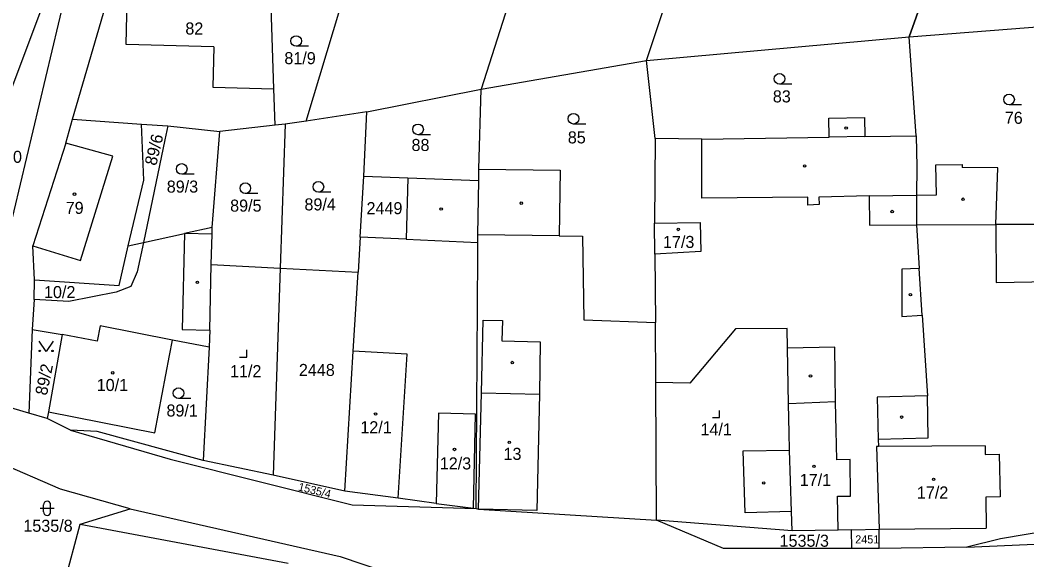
# Model space of a CAD drawing. Extents: x -801826 to -800592, y -1032871 to -1031813.
# Drawn here: x -801600 to -801458.2, y -1032298.8 to -1032222.7 of the extents above; entities that cross this region are included whole.
import ezdxf

# ---------------------------------------------------------------- set-up
doc = ezdxf.new("R2010")
doc.units = 0
for name, color, linetype in [('Vrstva 1', 7, 'Continuous'), ('Vrstva 18', 7, 'Continuous'), ('Vrstva 19', 7, 'Continuous'), ('Vrstva 25', 7, 'Continuous'), ('Vrstva 4', 7, 'Continuous')]:
    doc.layers.add(name, color=color, linetype=linetype)

msp = doc.modelspace()

# ---------------------------------------------------------------- linework, layer by layer
at = {"layer": 'Vrstva 1'}
for p, q in [((-801518.17, -1032179.53), (-801535.05, -1032232.41)), ((-801511.73, -1032228.35), (-801496.63, -1032182.4)), ((-801474.72, -1032225.02), (-801461.5, -1032187.46)), ((-801461.5, -1032187.46), (-801474.72, -1032225.02)), ((-801601.75, -1032253.31), (-801592.18, -1032213.05)), ((-801602.24, -1032235.1), (-801595.46, -1032216.99)), ((-801592.61, -1032236.62), (-801587.68, -1032219.71)), ((-801564.26, -1032232.36), (-801564.66, -1032220.77)), ((-801559.71, -1032236.89), (-801554.81, -1032220.67)), ((-801474.72, -1032225.02), (-801448.05, -1032222.93)), ((-801474.72, -1032225.02), (-801448.05, -1032222.93)), ((-801511.73, -1032228.35), (-801474.72, -1032225.02)), ((-801473.76, -1032238.96), (-801474.72, -1032225.02)), ((-801535.05, -1032232.41), (-801511.73, -1032228.35)), ((-801510.54, -1032239.34), (-801511.73, -1032228.35)), ((-801564.09, -1032237.49), (-801564.26, -1032232.36)), ((-801551.18, -1032235.59), (-801535.05, -1032232.41)), ((-801535.38, -1032243.68), (-801535.05, -1032232.41)), ((-801551.18, -1032235.59), (-801559.71, -1032236.89)), ((-801551.59, -1032244.67), (-801551.18, -1032235.59)), ((-801593.55, -1032240.02), (-801592.61, -1032236.62)), ((-801592.61, -1032236.62), (-801582.91, -1032237.31)), ((-801559.71, -1032236.89), (-801562.66, -1032237.33)), ((-801486.05, -1032236.46), (-801481.05, -1032236.38)), ((-801486.01, -1032239.16), (-801486.05, -1032236.46)), ((-801481.05, -1032236.38), (-801481.01, -1032239.08)), ((-801582.6, -1032245.23), (-801582.91, -1032237.31)), ((-801582.91, -1032237.31), (-801579.22, -1032237.56)), ((-801579.22, -1032237.56), (-801579.62, -1032239.55)), ((-801579.22, -1032237.56), (-801571.86, -1032238.35)), ((-801572.95, -1032251.88), (-801571.86, -1032238.35)), ((-801564.09, -1032237.49), (-801571.86, -1032238.35)), ((-801562.66, -1032237.33), (-801564.09, -1032237.49)), ((-801562.66, -1032237.33), (-801563.35, -1032257.61)), ((-801579.62, -1032239.55), (-801582.63, -1032254.03)), ((-801510.54, -1032239.34), (-801510.64, -1032251.27)), ((-801503.94, -1032239.45), (-801510.54, -1032239.34)), ((-801503.94, -1032239.45), (-801486.01, -1032239.16)), ((-801481.01, -1032239.08), (-801473.76, -1032238.96)), ((-801473.76, -1032238.96), (-801473.67, -1032243.33)), ((-801593.55, -1032240.02), (-801598.24, -1032254.48)), ((-801535.4, -1032245.25), (-801535.38, -1032243.68)), ((-801535.38, -1032243.68), (-801523.93, -1032243.83)), ((-801523.93, -1032243.83), (-801524.05, -1032253.08)), ((-801473.67, -1032243.33), (-801473.69, -1032247.35)), ((-801470.96, -1032243.08), (-801467.26, -1032243.03)), ((-801470.9, -1032247.31), (-801470.96, -1032243.08)), ((-801467.26, -1032243.03), (-801467.25, -1032243.42)), ((-801462.23, -1032243.48), (-801467.25, -1032243.42)), ((-801462.54, -1032251.48), (-801462.23, -1032243.48)), ((-801584.77, -1032254.5), (-801582.6, -1032245.23)), ((-801552.11, -1032253.25), (-801551.59, -1032244.67)), ((-801551.59, -1032244.67), (-801545.37, -1032244.89)), ((-801545.37, -1032244.89), (-801545.61, -1032253.56)), ((-801545.37, -1032244.89), (-801535.4, -1032245.25)), ((-801535.5, -1032252.93), (-801535.4, -1032245.25)), ((-801473.69, -1032247.35), (-801473.72, -1032251.53)), ((-801473.69, -1032247.35), (-801470.9, -1032247.31)), ((-801510.64, -1032251.27), (-801504.21, -1032251.17)), ((-801504.21, -1032251.17), (-801504.08, -1032255.3)), ((-801572.95, -1032251.88), (-801576.86, -1032252.75)), ((-801572.97, -1032252.84), (-801572.95, -1032251.88)), ((-801510.56, -1032255.64), (-801510.64, -1032251.27)), ((-801473.72, -1032251.53), (-801473.33, -1032257.67)), ((-801446.08, -1032251.42), (-801462.54, -1032251.48)), ((-801584.77, -1032254.5), (-801582.63, -1032254.03)), ((-801582.63, -1032254.03), (-801583.5, -1032258.17)), ((-801582.63, -1032254.03), (-801576.86, -1032252.75)), ((-801573.07, -1032257.1), (-801572.97, -1032252.84)), ((-801552.11, -1032253.25), (-801552.4, -1032258.18)), ((-801545.61, -1032253.56), (-801552.11, -1032253.25)), ((-801535.54, -1032255.79), (-801535.52, -1032254.03)), ((-801535.52, -1032254.03), (-801535.5, -1032252.93)), ((-801524.05, -1032253.08), (-801520.75, -1032253.12)), ((-801520.75, -1032253.12), (-801520.58, -1032264.93)), ((-801597.97, -1032259.28), (-801598.24, -1032254.48)), ((-801586.07, -1032260.09), (-801584.77, -1032254.5)), ((-801504.08, -1032255.3), (-801510.56, -1032255.64)), ((-801535.77, -1032291.53), (-801535.54, -1032255.79)), ((-801510.56, -1032255.64), (-801510.5, -1032265.3)), ((-801583.5, -1032258.17), (-801584.42, -1032260.22)), ((-801573.3, -1032266.37), (-801573.07, -1032257.1)), ((-801573.07, -1032257.1), (-801563.35, -1032257.61)), ((-801563.35, -1032257.61), (-801564.34, -1032286.8)), ((-801563.35, -1032257.61), (-801552.4, -1032258.18)), ((-801553.07, -1032269.31), (-801552.4, -1032258.18)), ((-801472.91, -1032264.26), (-801473.33, -1032257.67)), ((-801598.05, -1032262.06), (-801597.97, -1032259.28)), ((-801597.97, -1032259.28), (-801586.07, -1032260.09)), ((-801586.49, -1032261.01), (-801593.17, -1032262.33)), ((-801584.42, -1032260.22), (-801586.49, -1032261.01)), ((-801598.05, -1032262.06), (-801598.3, -1032266.26)), ((-801593.17, -1032262.33), (-801598.05, -1032262.06)), ((-801520.58, -1032264.93), (-801510.5, -1032265.3)), ((-801510.43, -1032273.74), (-801510.5, -1032265.3)), ((-801472.91, -1032264.26), (-801472.18, -1032275.64)), ((-801598.3, -1032266.26), (-801598.78, -1032278.08)), ((-801598.3, -1032266.26), (-801594.07, -1032266.96)), ((-801573.3, -1032266.37), (-801573.36, -1032268.79)), ((-801499.2, -1032266.19), (-801505.63, -1032273.86)), ((-801491.92, -1032266.15), (-801499.2, -1032266.19)), ((-801491.88, -1032268.92), (-801491.92, -1032266.15)), ((-801594.07, -1032266.96), (-801596.03, -1032277.89)), ((-801578.96, -1032269.95), (-801578.53, -1032267.77)), ((-801573.36, -1032268.79), (-801578.53, -1032267.77)), ((-801573.36, -1032268.79), (-801574.23, -1032284.75)), ((-801554.26, -1032289.08), (-801553.07, -1032269.31)), ((-801491.74, -1032276.76), (-801491.88, -1032268.92)), ((-801581.04, -1032280.87), (-801578.96, -1032269.95)), ((-801510.33, -1032293.14), (-801510.43, -1032273.74)), ((-801505.63, -1032273.86), (-801510.43, -1032273.74)), ((-801491.67, -1032280.87), (-801491.74, -1032276.76)), ((-801472.18, -1032275.64), (-801479.26, -1032275.81)), ((-801479.26, -1032275.81), (-801479.1, -1032281.72)), ((-801598.78, -1032278.08), (-801602.13, -1032277.11)), ((-801596.22, -1032278.82), (-801598.78, -1032278.08)), ((-801596.03, -1032277.89), (-801596.22, -1032278.82)), ((-801596.03, -1032277.89), (-801581.04, -1032280.87)), ((-801541.05, -1032278.09), (-801541.38, -1032290.79)), ((-801535.86, -1032278.23), (-801541.05, -1032278.09)), ((-801592.93, -1032280.48), (-801596.22, -1032278.82)), ((-801536.13, -1032291.45), (-801535.86, -1032278.23)), ((-801589.14, -1032280.68), (-801592.93, -1032280.48)), ((-801592.93, -1032280.48), (-801578.89, -1032284.57)), ((-801574.23, -1032284.75), (-801589.14, -1032280.68)), ((-801491.6, -1032283.27), (-801491.67, -1032280.87)), ((-801479.1, -1032281.72), (-801479.07, -1032282.77)), ((-801498.15, -1032283.39), (-801491.6, -1032283.27)), ((-801497.85, -1032292.13), (-801498.15, -1032283.39)), ((-801479.07, -1032282.77), (-801479.32, -1032282.77)), ((-801479.32, -1032282.77), (-801478.99, -1032294.44)), ((-801594.32, -1032288.81), (-801604.36, -1032284.46)), ((-801578.89, -1032284.57), (-801553.23, -1032291.01)), ((-801564.34, -1032286.8), (-801574.23, -1032284.75)), ((-801554.26, -1032289.08), (-801564.34, -1032286.8)), ((-801584.52, -1032291.54), (-801594.32, -1032288.81)), ((-801546.73, -1032290.08), (-801554.26, -1032289.08)), ((-801541.38, -1032290.79), (-801546.73, -1032290.08)), ((-801541.38, -1032290.79), (-801536.13, -1032291.45)), ((-801591.53, -1032293.73), (-801584.52, -1032291.54)), ((-801584.52, -1032291.54), (-801554.92, -1032298.29)), ((-801553.23, -1032291.01), (-801535.77, -1032291.53)), ((-801536.13, -1032291.45), (-801535.77, -1032291.53)), ((-801535.77, -1032291.53), (-801535.41, -1032291.6)), ((-801535.41, -1032291.6), (-801510.33, -1032293.14)), ((-801491.3, -1032291.96), (-801497.85, -1032292.13)), ((-801491.22, -1032294.67), (-801491.3, -1032291.96)), ((-801594.62, -1032305.08), (-801591.53, -1032293.73)), ((-801591.53, -1032293.73), (-801562.22, -1032299.23)), ((-801491.22, -1032294.67), (-801510.33, -1032293.14)), ((-801500.88, -1032297.15), (-801510.33, -1032293.14)), ((-801444.94, -1032292.94), (-801461.89, -1032295.77)), ((-801484.74, -1032294.56), (-801491.22, -1032294.67)), ((-801482.85, -1032294.53), (-801484.74, -1032294.56)), ((-801482.85, -1032294.53), (-801478.99, -1032294.44)), ((-801482.83, -1032297.14), (-801482.85, -1032294.53)), ((-801478.98, -1032297.14), (-801478.99, -1032294.44)), ((-801466.62, -1032296.97), (-801423.3, -1032295.08)), ((-801461.89, -1032295.77), (-801466.62, -1032296.97)), ((-801482.83, -1032297.14), (-801500.88, -1032297.15)), ((-801478.98, -1032297.14), (-801482.83, -1032297.14)), ((-801466.62, -1032296.97), (-801478.98, -1032297.14)), ((-801554.92, -1032298.29), (-801545.05, -1032301.61))]:
    msp.add_line(p, q, dxfattribs=at)
at = {"layer": 'Vrstva 25'}
for p, q in [((-801559.37, -1032226.35), (-801561.12, -1032226.35)), ((-801491.27, -1032231.69), (-801493.02, -1032231.69)), ((-801458.92, -1032234.59), (-801460.67, -1032234.59)), ((-801520.29, -1032237.31), (-801522.04, -1032237.31)), ((-801542.19, -1032238.81), (-801543.94, -1032238.81)), ((-801575.49, -1032244.39), (-801577.24, -1032244.39)), ((-801556.24, -1032246.92), (-801557.99, -1032246.92)), ((-801566.53, -1032247.1), (-801568.28, -1032247.1)), ((-801568.08, -1032270.16), (-801568.08, -1032269.16)), ((-801569.08, -1032270.16), (-801568.08, -1032270.16)), ((-801575.94, -1032276.01), (-801577.69, -1032276.01)), ((-801501.46, -1032278.69), (-801501.46, -1032277.69)), ((-801502.46, -1032278.69), (-801501.46, -1032278.69)), ((-801597.21, -1032291.49), (-801595.21, -1032291.49)), ((-801596.71, -1032291.99), (-801596.71, -1032290.99)), ((-801595.71, -1032291.99), (-801595.71, -1032290.99))]:
    msp.add_line(p, q, dxfattribs=at)
msp.add_lwpolyline([(-801595.35, -1032267.9), (-801596.35, -1032269.4), (-801597.35, -1032267.9)], dxfattribs=at)
for centre, radius in [((-801561.12, -1032225.6), 0.75), ((-801493.02, -1032230.94), 0.75), ((-801460.67, -1032233.84), 0.75), ((-801522.04, -1032236.56), 0.75), ((-801543.94, -1032238.06), 0.75), ((-801483.62, -1032237.87), 0.175), ((-801577.24, -1032243.64), 0.75), ((-801489.47, -1032243.22), 0.175), ((-801557.99, -1032246.17), 0.75), ((-801568.28, -1032246.35), 0.75), ((-801592.35, -1032247.2), 0.175), ((-801529.39, -1032248.47), 0.175), ((-801467.15, -1032247.91), 0.175), ((-801540.69, -1032249.29), 0.175), ((-801477.13, -1032249.65), 0.175), ((-801507.27, -1032252.17), 0.175), ((-801575.03, -1032259.63), 0.175), ((-801474.56, -1032261.36), 0.175), ((-801597.25, -1032269.3), 0.1), ((-801595.45, -1032269.3), 0.1), ((-801530.66, -1032270.94), 0.175), ((-801586.96, -1032272.39), 0.175), ((-801488.64, -1032272.83), 0.175), ((-801577.69, -1032275.26), 0.75), ((-801549.93, -1032278.2), 0.175), ((-801475.81, -1032278.63), 0.175), ((-801531.09, -1032282.18), 0.175), ((-801538.8, -1032283.19), 0.175), ((-801488.15, -1032285.56), 0.175), ((-801495.24, -1032287.91), 0.175), ((-801471.29, -1032287.41), 0.175)]:
    msp.add_circle(centre, radius, dxfattribs=at)
for centre, start, end in [((-801596.21, -1032290.99), 0, 180), ((-801596.21, -1032291.99), 180, 0)]:
    msp.add_arc(centre, 0.5, start, end, dxfattribs=at)
at = {"layer": 'Vrstva 4'}
for p, q in [((-801585.09, -1032226.1), (-801584.92, -1032219.84)), ((-801572.72, -1032226.44), (-801585.09, -1032226.1)), ((-801572.72, -1032226.44), (-801572.88, -1032232.12)), ((-801572.88, -1032232.12), (-801564.26, -1032232.36)), ((-801503.95, -1032247.77), (-801503.94, -1032239.45)), ((-801481.01, -1032239.08), (-801486.01, -1032239.16)), ((-801586.97, -1032241.85), (-801593.55, -1032240.02)), ((-801591.5, -1032256.54), (-801586.97, -1032241.85)), ((-801489.02, -1032247.61), (-801503.95, -1032247.77)), ((-801489.01, -1032248.77), (-801489.02, -1032247.61)), ((-801480.37, -1032247.44), (-801487.46, -1032247.62)), ((-801487.46, -1032247.62), (-801487.42, -1032248.67)), ((-801480.37, -1032247.44), (-801473.69, -1032247.35)), ((-801480.37, -1032247.44), (-801480.35, -1032251.59)), ((-801487.42, -1032248.67), (-801489.01, -1032248.77)), ((-801480.35, -1032251.59), (-801473.72, -1032251.53)), ((-801473.72, -1032251.53), (-801462.54, -1032251.48)), ((-801462.54, -1032251.48), (-801462.46, -1032259.63)), ((-801576.86, -1032252.75), (-801577.19, -1032266.28)), ((-801572.97, -1032252.84), (-801576.86, -1032252.75)), ((-801545.61, -1032253.56), (-801535.52, -1032254.03)), ((-801524.05, -1032253.08), (-801535.5, -1032252.93)), ((-801598.24, -1032254.48), (-801591.5, -1032256.54)), ((-801473.33, -1032257.67), (-801475.78, -1032257.76)), ((-801475.78, -1032257.76), (-801475.77, -1032264.46)), ((-801462.46, -1032259.63), (-801446.01, -1032259.36)), ((-801535.01, -1032275.2), (-801534.76, -1032264.96)), ((-801534.76, -1032264.96), (-801532.06, -1032265.02)), ((-801532.06, -1032265.02), (-801532.13, -1032267.87)), ((-801475.77, -1032264.46), (-801472.91, -1032264.26)), ((-801588.73, -1032265.75), (-801589.17, -1032267.93)), ((-801578.53, -1032267.77), (-801588.73, -1032265.75)), ((-801577.19, -1032266.28), (-801573.3, -1032266.37)), ((-801589.17, -1032267.93), (-801594.07, -1032266.96)), ((-801532.13, -1032267.87), (-801526.74, -1032268)), ((-801526.74, -1032268), (-801526.81, -1032275.4)), ((-801545.49, -1032269.77), (-801553.07, -1032269.31)), ((-801485.2, -1032268.75), (-801491.88, -1032268.92)), ((-801485.1, -1032276.48), (-801485.2, -1032268.75)), ((-801546.73, -1032290.08), (-801545.49, -1032269.77)), ((-801535.41, -1032291.6), (-801535.01, -1032275.2)), ((-801535.01, -1032275.2), (-801526.81, -1032275.4)), ((-801526.81, -1032275.4), (-801527.21, -1032291.8)), ((-801485.1, -1032276.48), (-801491.74, -1032276.76)), ((-801485.03, -1032280.52), (-801485.1, -1032276.48)), ((-801472.04, -1032281.55), (-801472.18, -1032275.64)), ((-801484.94, -1032284.65), (-801485.03, -1032280.52)), ((-801479.1, -1032281.72), (-801472.04, -1032281.55)), ((-801491.3, -1032291.96), (-801491.6, -1032283.27)), ((-801464.02, -1032282.67), (-801479.07, -1032282.77)), ((-801464.02, -1032282.67), (-801464.01, -1032283.9)), ((-801464.01, -1032283.9), (-801462.04, -1032283.85)), ((-801462.04, -1032283.85), (-801461.91, -1032289.89)), ((-801483.05, -1032284.63), (-801484.94, -1032284.65)), ((-801482.99, -1032289.8), (-801483.05, -1032284.63)), ((-801484.74, -1032294.56), (-801484.82, -1032289.8)), ((-801484.82, -1032289.8), (-801482.99, -1032289.8)), ((-801461.91, -1032289.89), (-801463.94, -1032289.92)), ((-801463.94, -1032289.92), (-801463.89, -1032294.27)), ((-801527.21, -1032291.8), (-801535.41, -1032291.6)), ((-801478.99, -1032294.44), (-801463.89, -1032294.27))]:
    msp.add_line(p, q, dxfattribs=at)

# ---------------------------------------------------------------- texts
at = {"layer": 'Vrstva 18'}
for s, height, p in [('81/9', 1.7, (-801562.78, -1032228.87)), ('83', 1.7, (-801493.95, -1032234.26)), ('76', 1.7, (-801461.27, -1032237.28)), ('85', 1.7, (-801522.84, -1032240.04)), ('88', 1.7, (-801544.86, -1032241.11)), ('90', 1.7, (-801602.28, -1032242.78)), ('89/3', 1.7, (-801579.35, -1032246.98)), ('89/5', 1.7, (-801570.42, -1032249.66)), ('89/4', 1.7, (-801559.95, -1032249.49)), ('2449', 1.7, (-801551.2, -1032250.02)), ('2448', 1.7, (-801560.73, -1032272.83)), ('89/1', 1.7, (-801579.39, -1032278.55)), ('1535/8', 1.7, (-801599.56, -1032294.8)), ('1535/3', 1.7, (-801493, -1032296.91)), ('2451', 1.14, (-801482.34, -1032296.44))]:
    msp.add_text(s, height=height, dxfattribs=at).set_placement(p)
for s, height, rotation, p in [('89/6', 1.7, 76.4736, (-801580.84, -1032243.27)), ('89/2', 1.7, 78.3971, (-801596.25, -1032275.66)), ('1535/4', 1.14, 346.185, (-801560.91, -1032288.95))]:
    msp.add_text(s, height=height, rotation=rotation, dxfattribs=at).set_placement(p)
at = {"layer": 'Vrstva 19'}
for s, p in [('82', (-801576.73, -1032224.69)), ('79', (-801593.59, -1032249.98)), ('17/3', (-801509.43, -1032254.78)), ('10/2', (-801596.65, -1032261.85)), ('11/2', (-801570.44, -1032273)), ('10/1', (-801589.22, -1032274.95)), ('12/1', (-801552.07, -1032280.91)), ('14/1', (-801504.15, -1032281.22)), ('13', (-801531.9, -1032284.66)), ('12/3', (-801540.88, -1032286.01)), ('17/1', (-801490.16, -1032288.34)), ('17/2', (-801473.65, -1032290.11))]:
    msp.add_text(s, height=1.7, dxfattribs=at).set_placement(p)

doc.saveas('drawing.dxf')
